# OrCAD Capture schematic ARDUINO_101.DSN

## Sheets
1 04: IO_ARDUINO_5V_Tol: size Custom; title: ARDUNIO 101; rev: 1; company: New Devices Group; note: SCHEM FOR TA=H94227
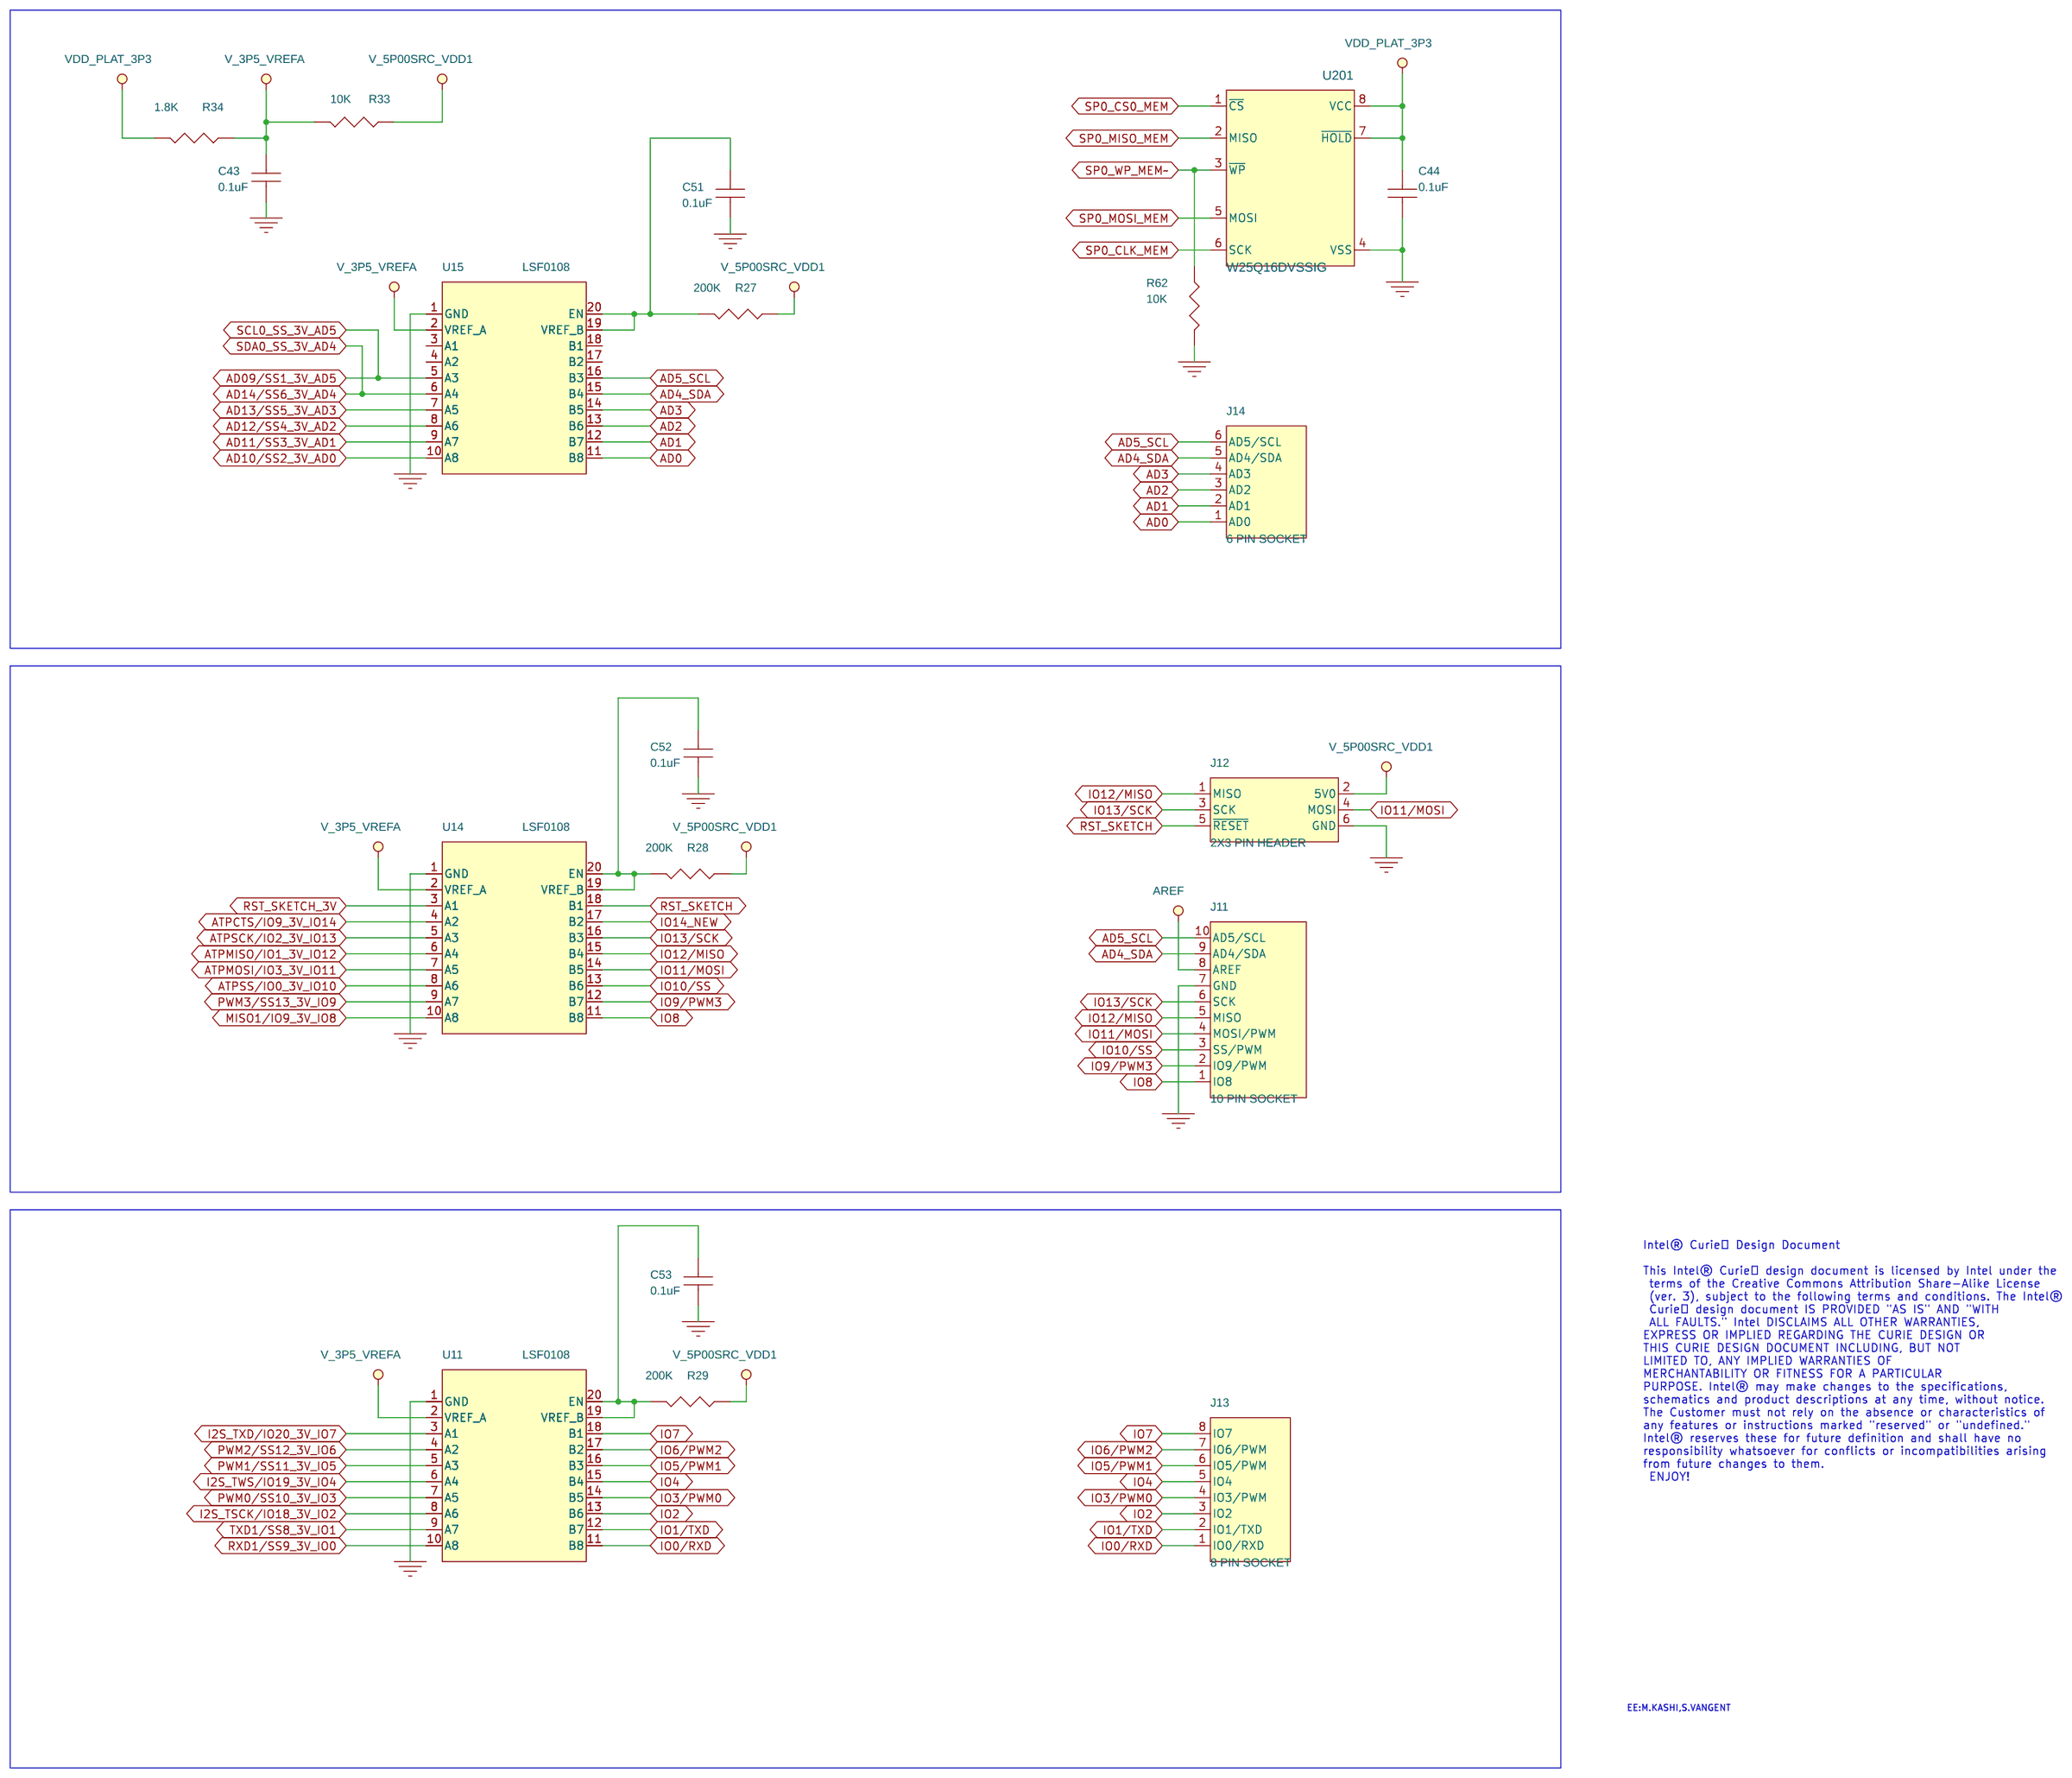
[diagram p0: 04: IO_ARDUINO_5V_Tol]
2 03: Curie: size Custom; rev: A
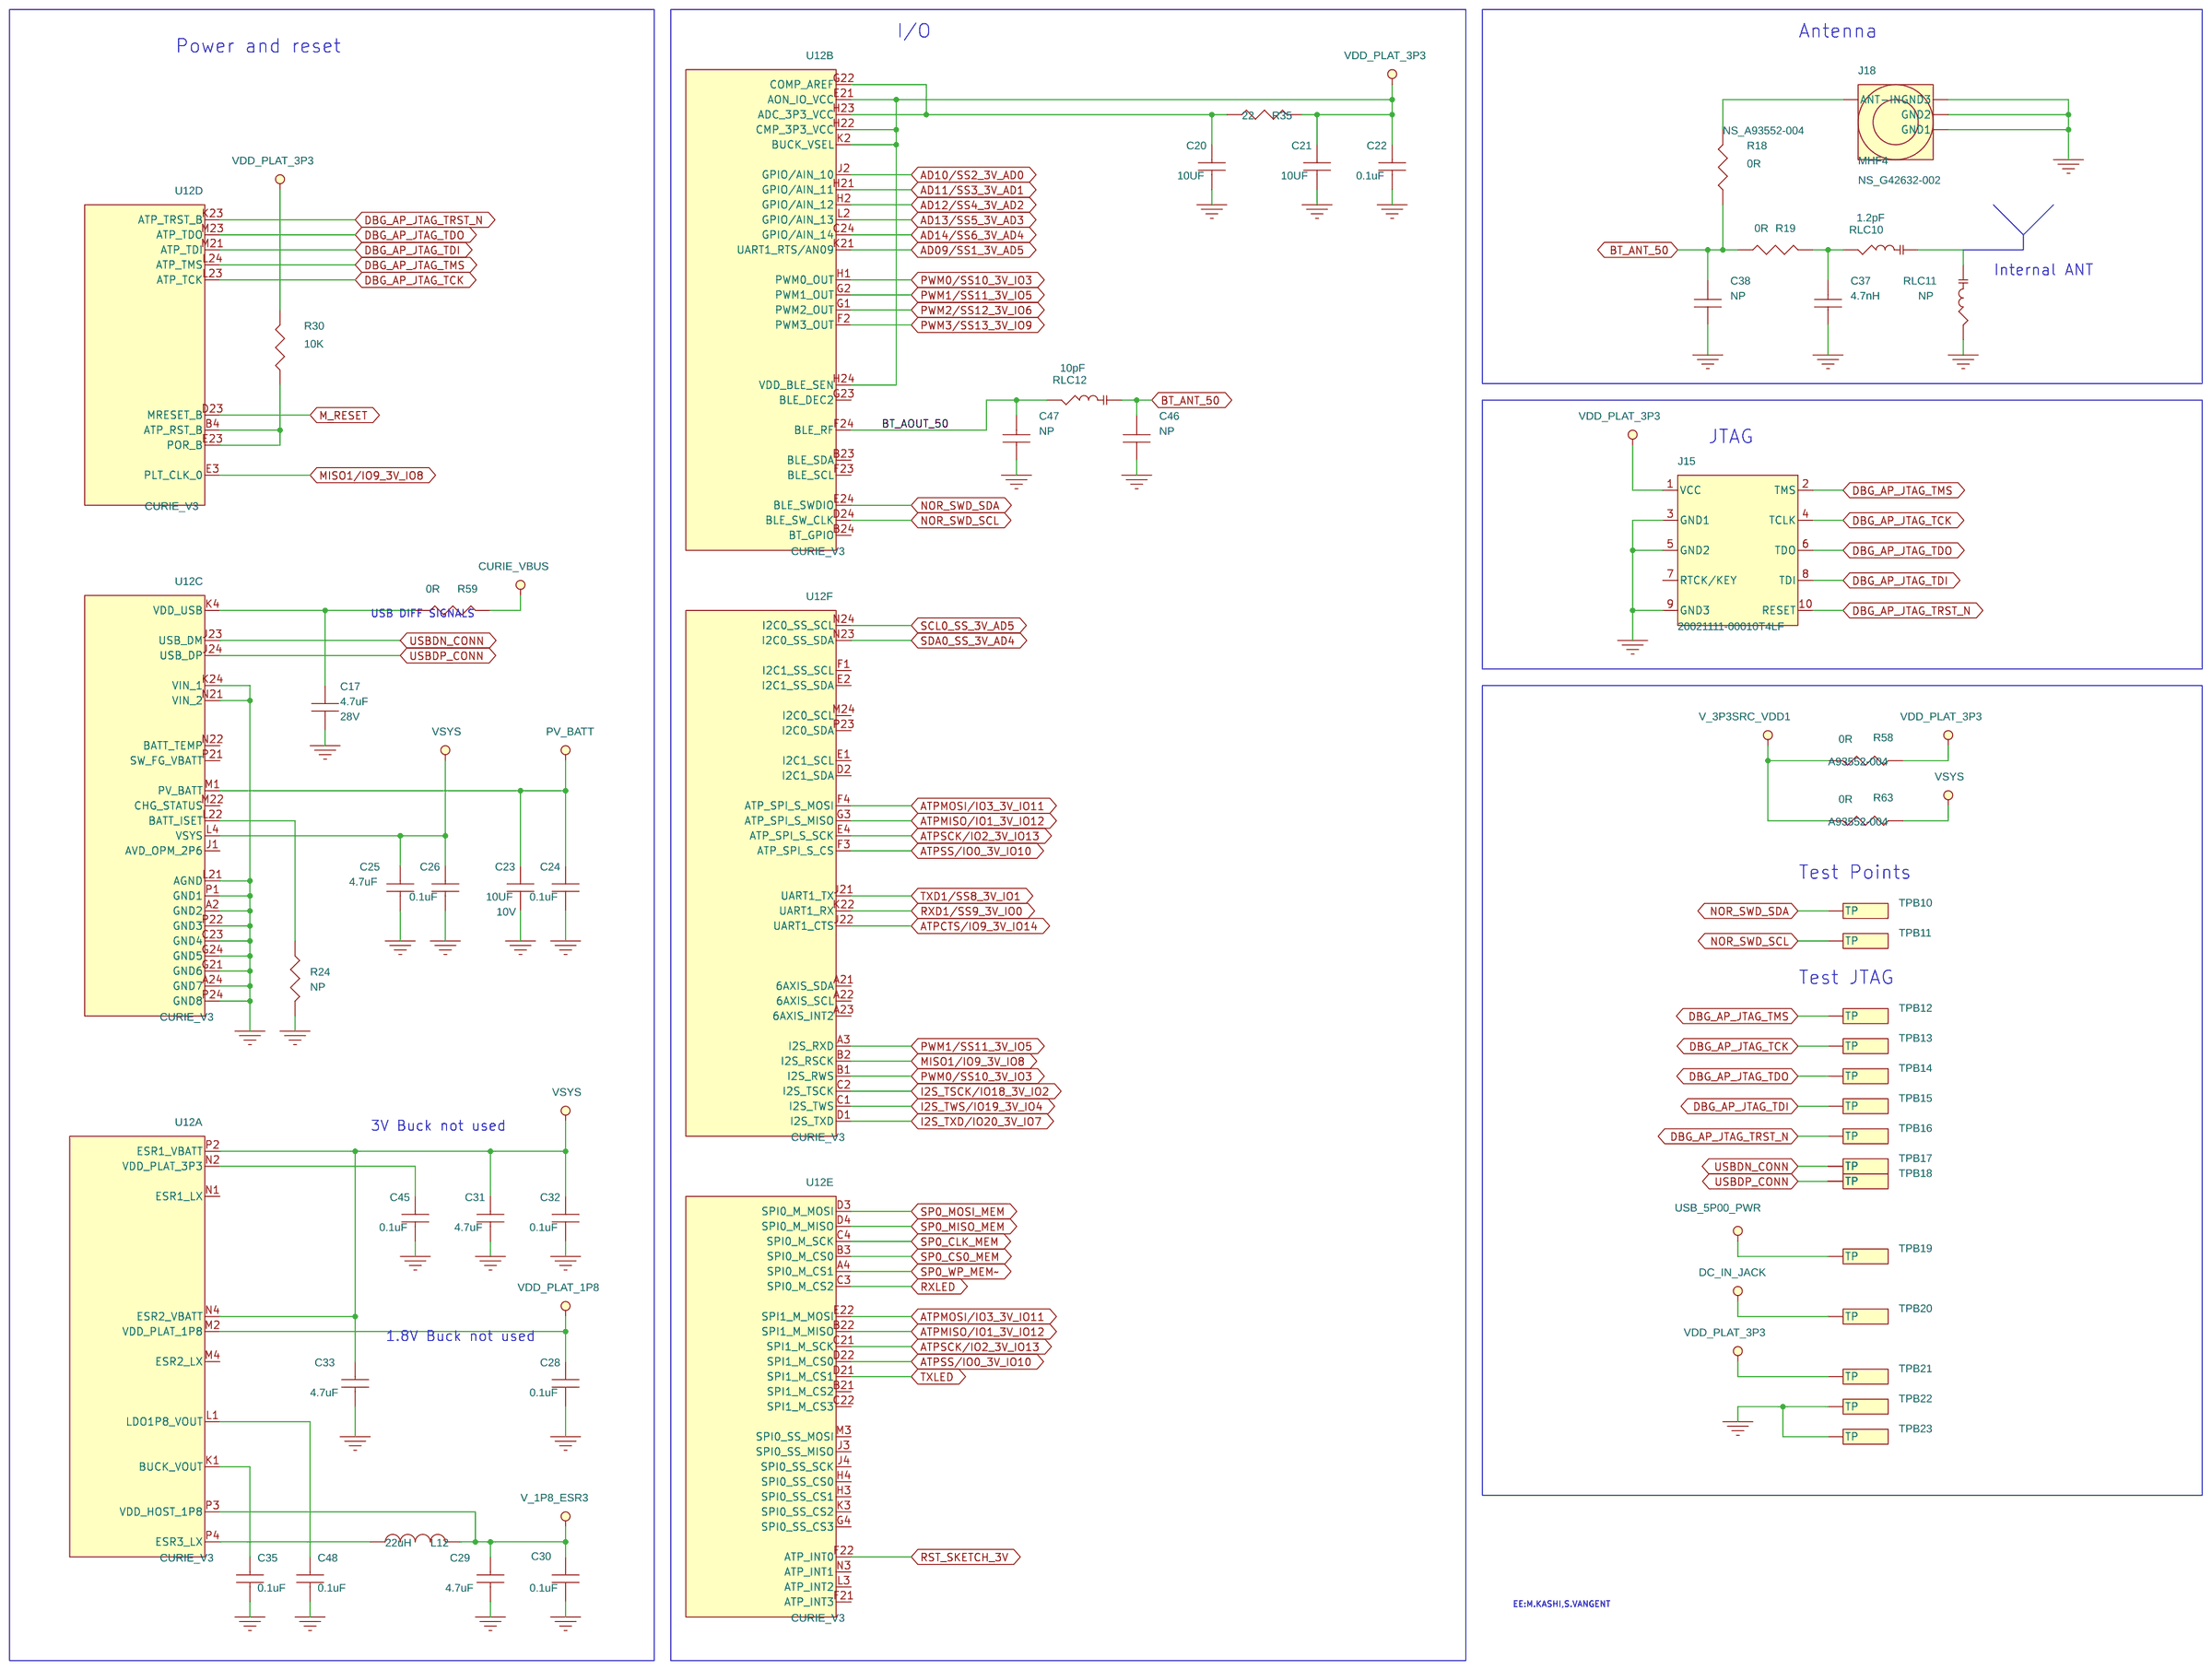
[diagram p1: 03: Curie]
3 02: Power & Connectors: size Custom
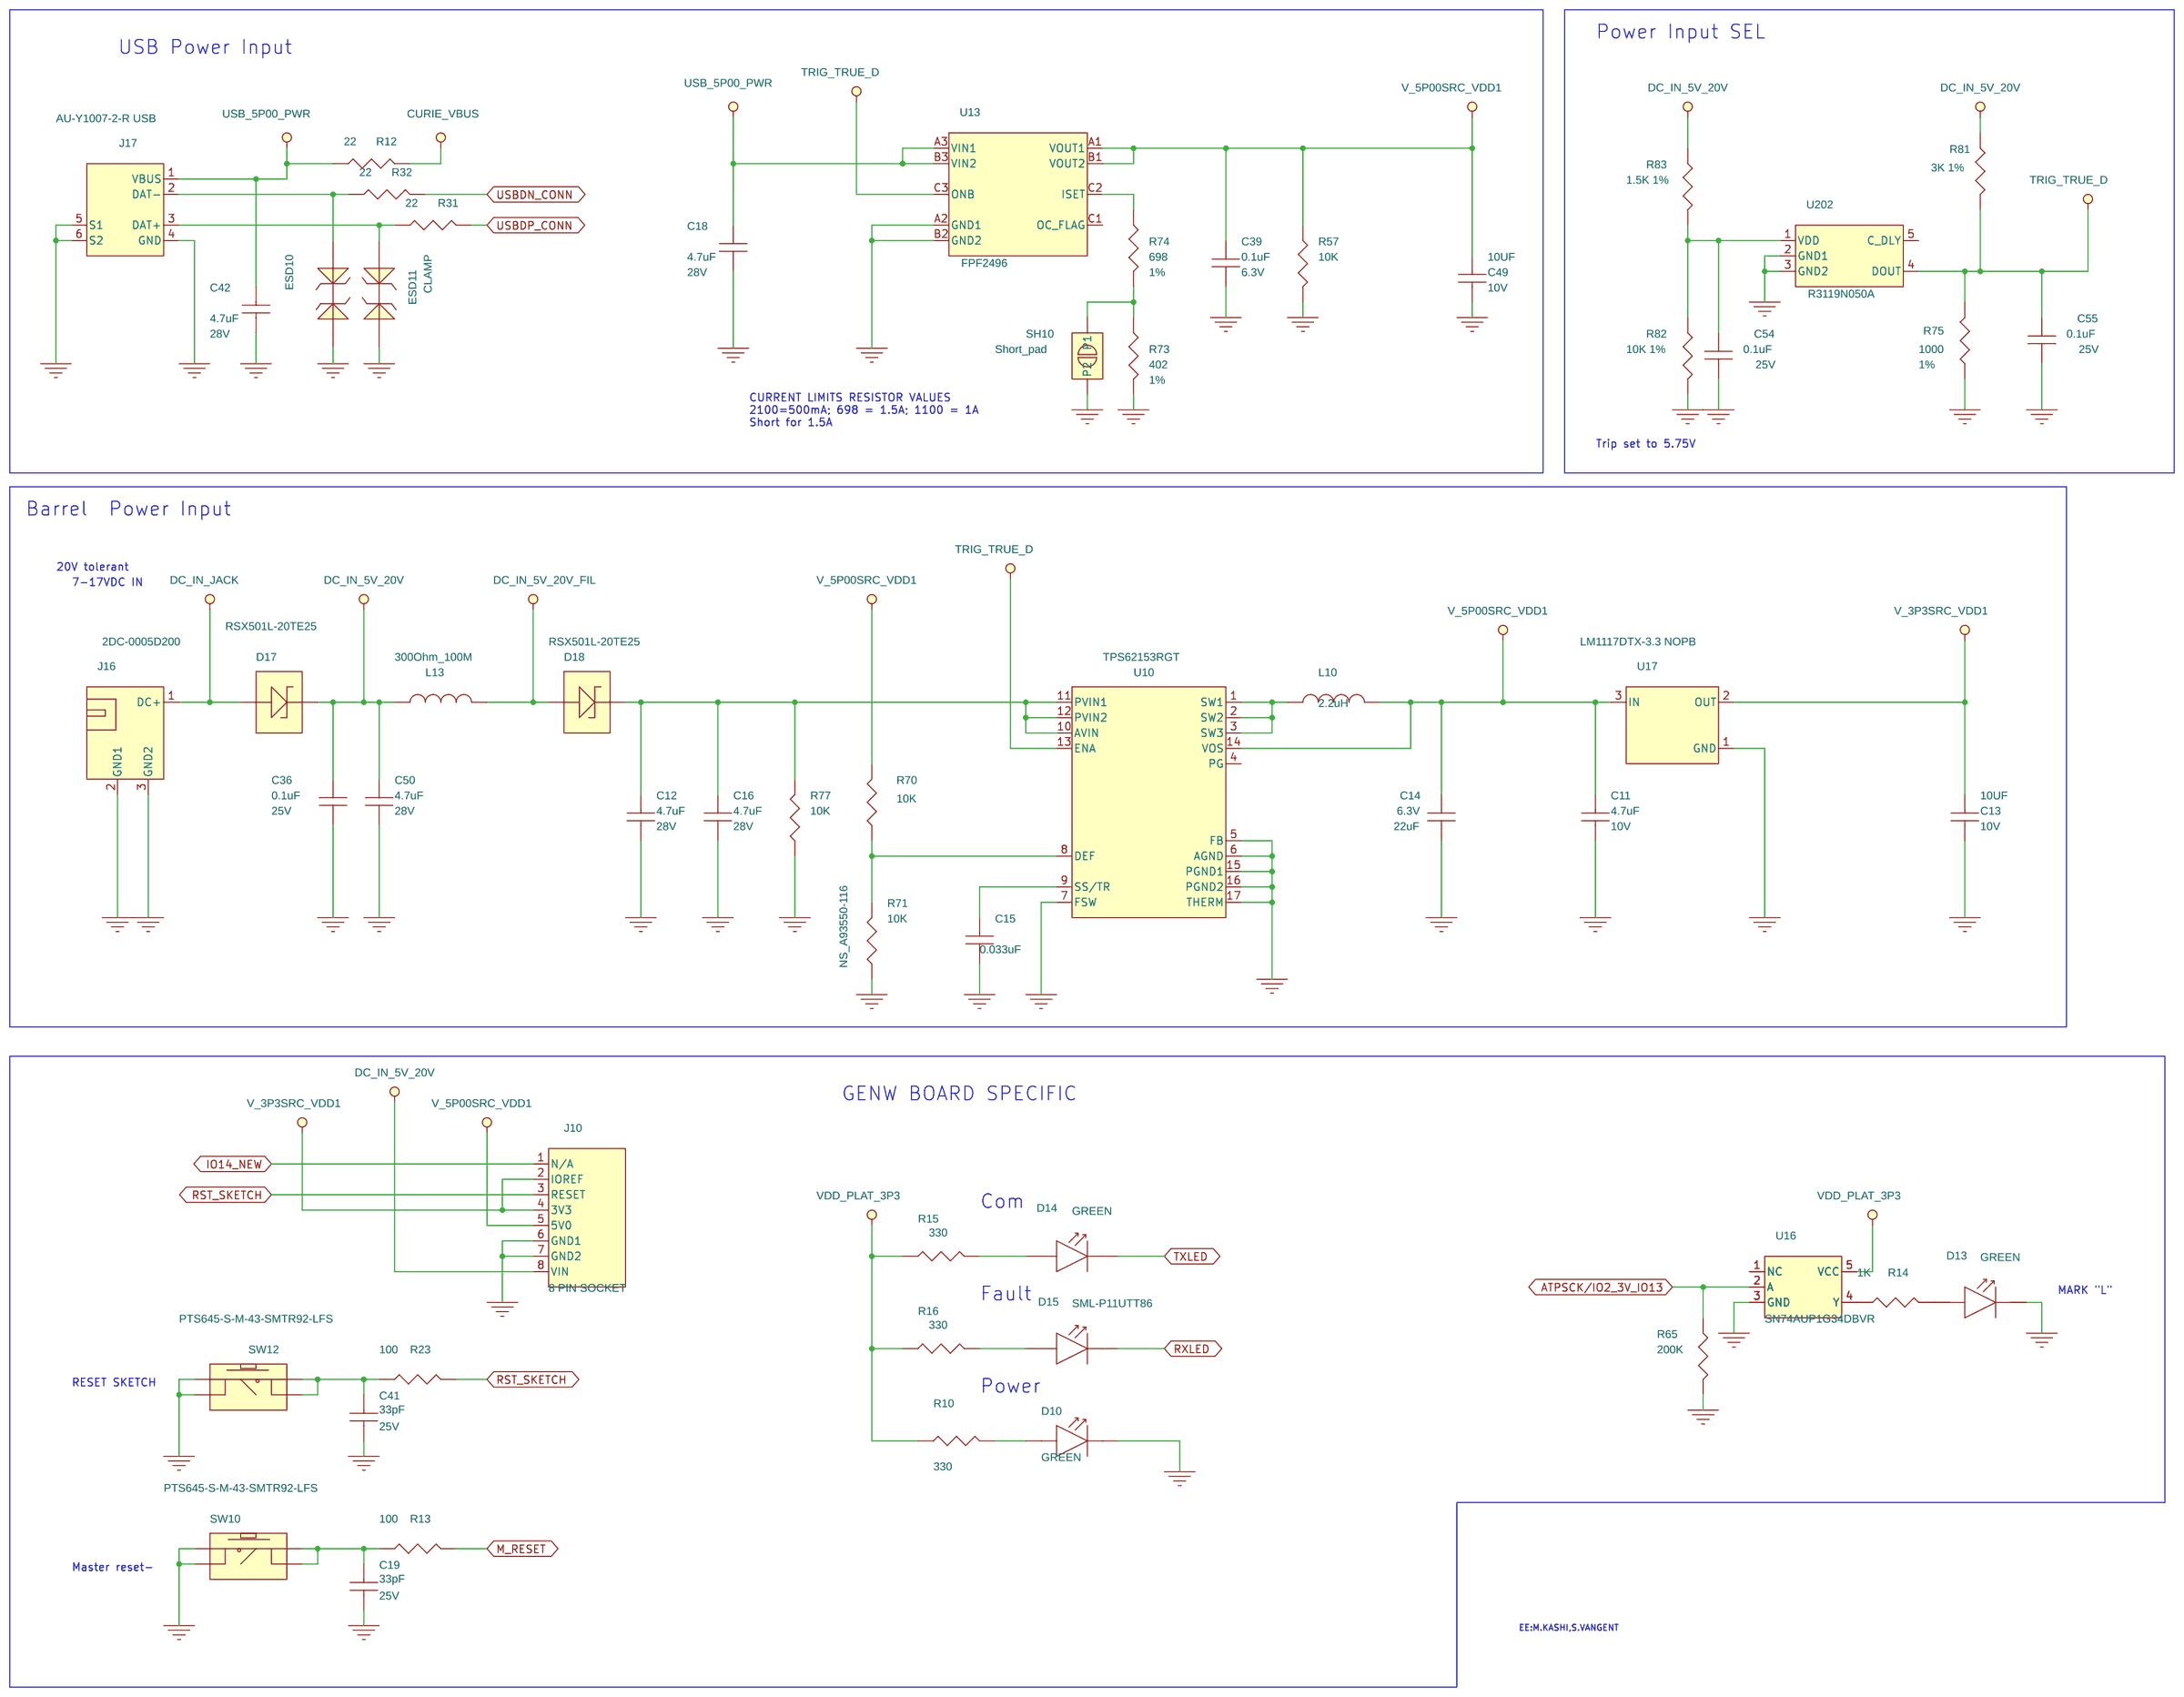
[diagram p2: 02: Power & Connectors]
4 01: Block Diagram and Revs
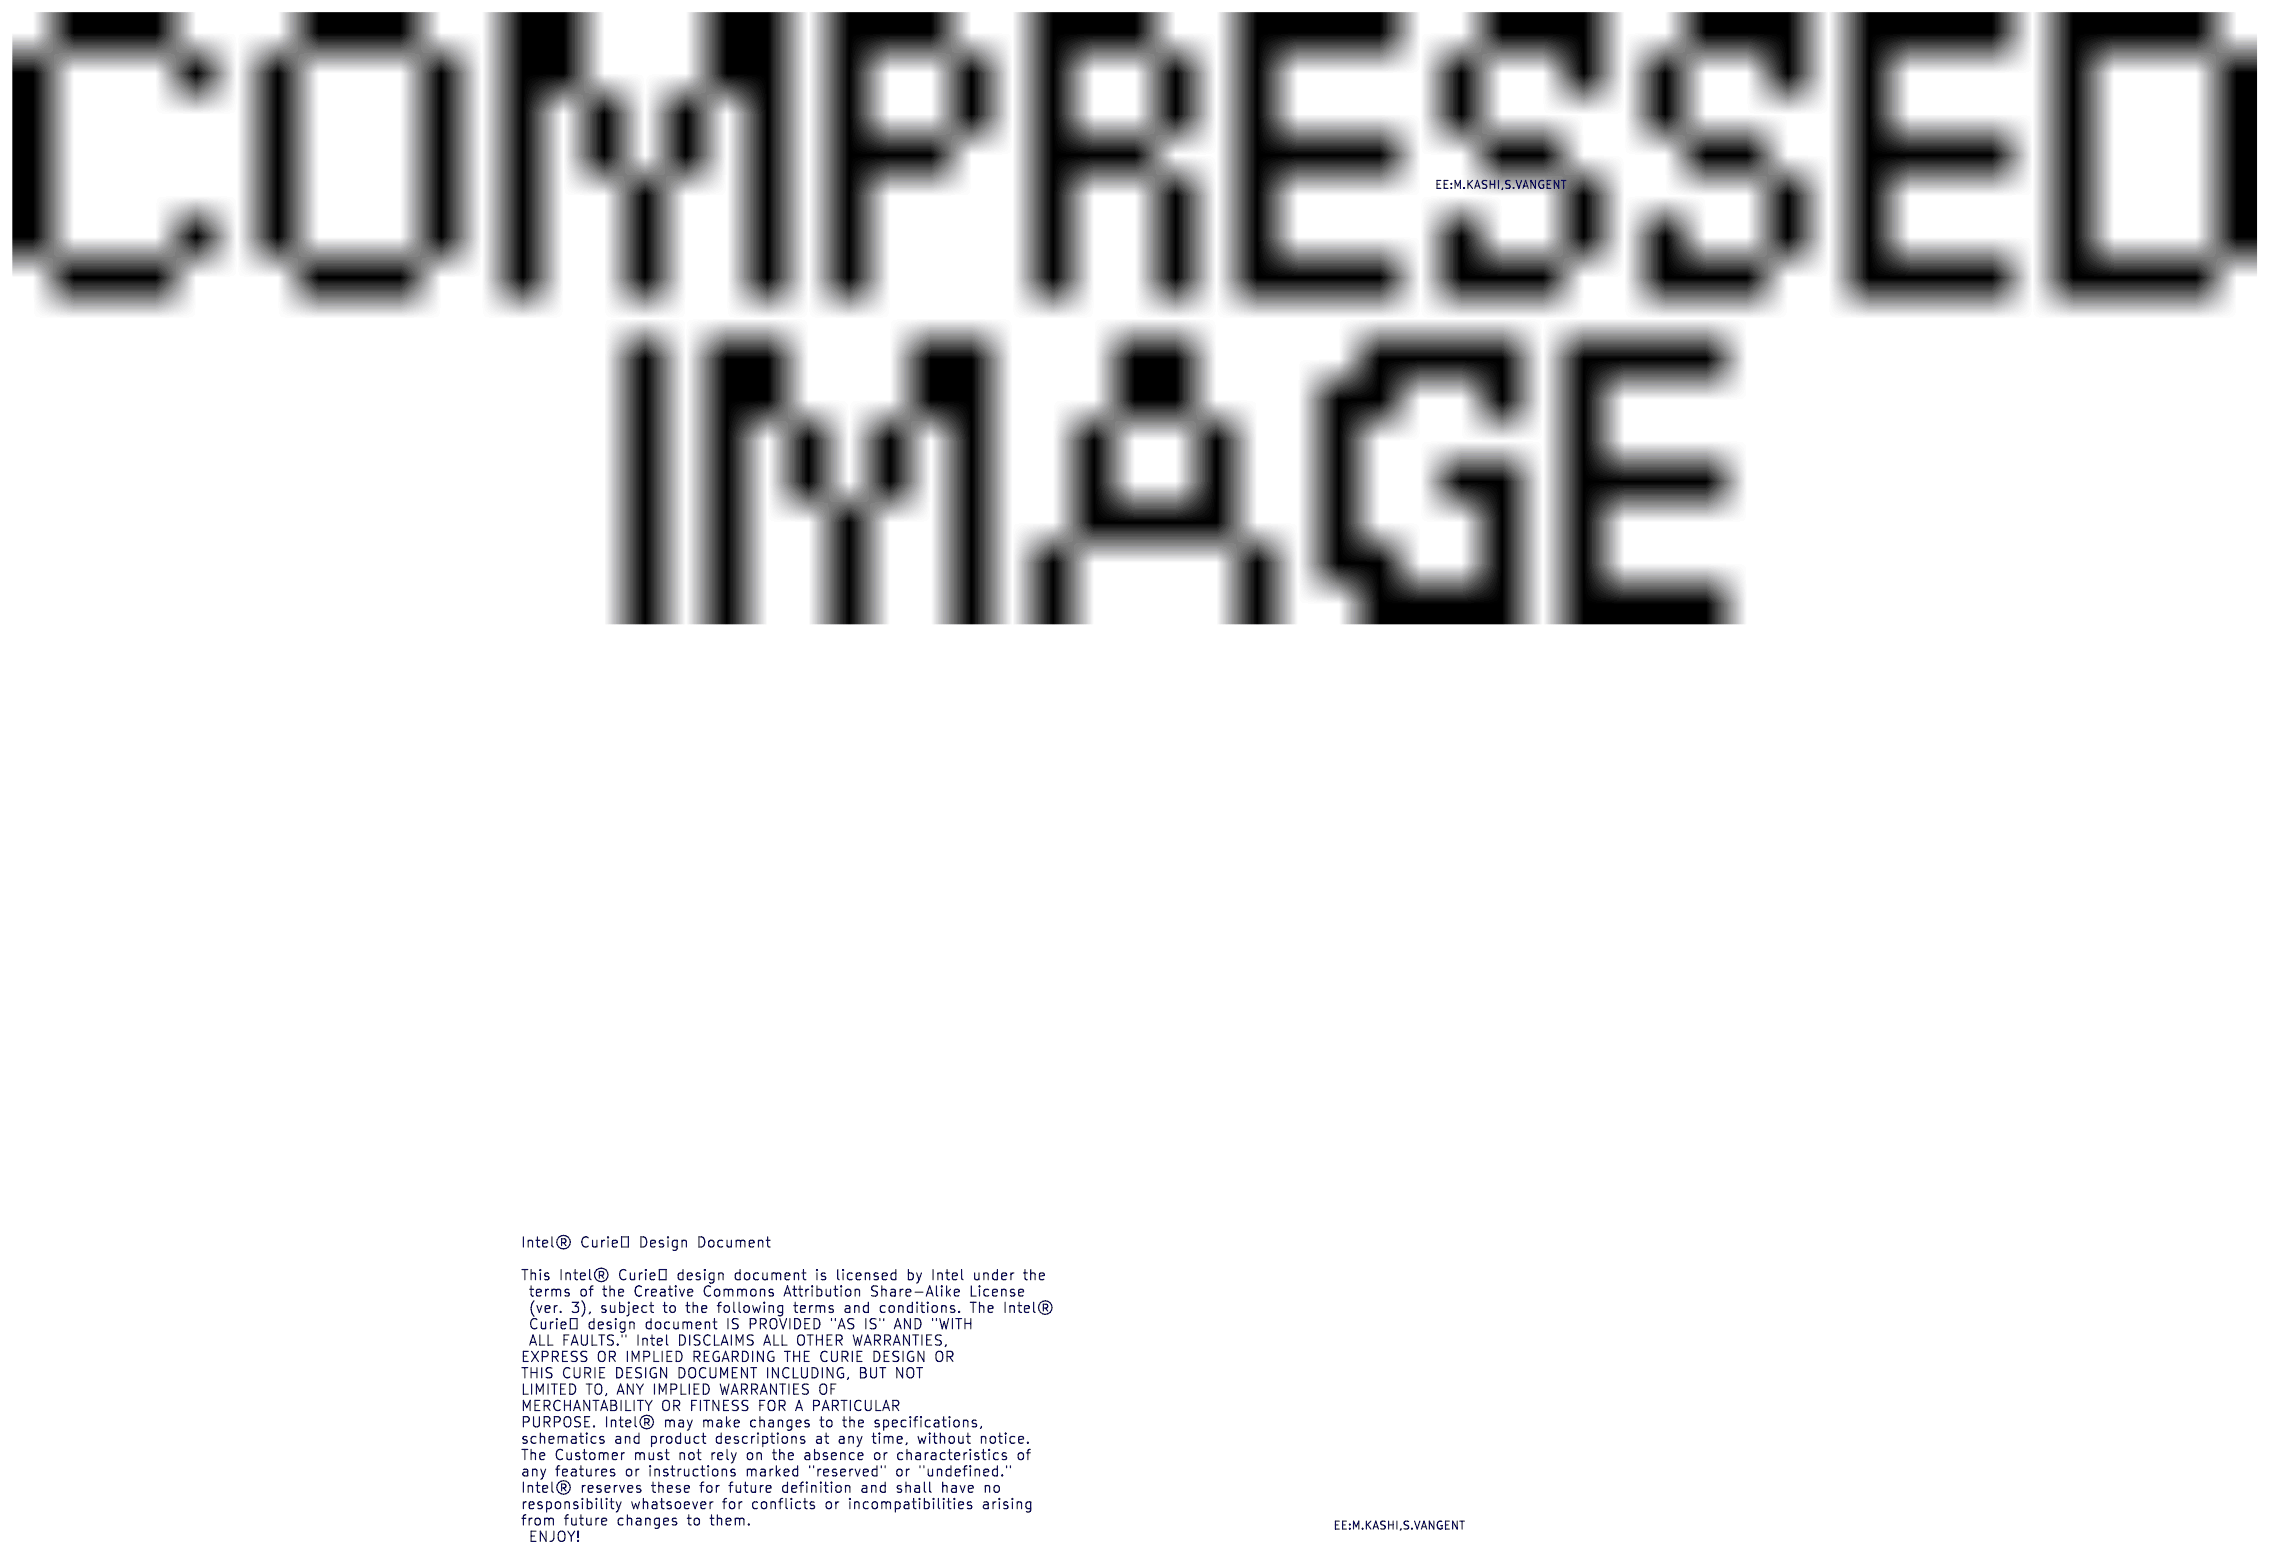
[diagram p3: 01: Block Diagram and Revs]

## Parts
sheet 02: Power & Connectors
C11  4.7uF  [0603X90H]
C12  4.7uF  [0603X90H]
C13  10UF  [0603X90H]
C14  22uF  [0603X90H]
C15  0.033uF  [0603X90H]
C16  4.7uF  [0603X90H]
C18  4.7uF  [0603X90H]
C19  33pF  [0603X90H]
C36  0.1uF  [0603X90H]
C39  0.1uF  [0603X90H]
C41  33pF  [0603X90H]
C42  4.7uF  [0603X90H]
C49  10UF  [0603X90H]
C50  4.7uF  [0603X90H]
C54  0.1uF  [0603X90H]
C55  0.1uF  [0603X90H]
D10  GREEN  [LED_100X60X25H_SMLP13]
D13  GREEN  [LED_100X60X25H_SMLP13]
D14  GREEN  [LED_100X60X25H_SMLP13]
D15  SML-P11UTT86  [LED_100X60X25H_SMLP13]
D17  RSX501L-20TE25  [DIO2_450X260X220H]
D18  RSX501L-20TE25  [DIO2_450X260X220H]
ESD10  CLAMP  [DIO_SOD882]
ESD11  CLAMP  [DIO_SOD882]
J10  8 PIN SOCKET  [CONF1X8-254P_2104X240X850H_TH]
J16  2DC-0005D200  [CON_JACK_880X1350X1135H_EJ508A]
J17  AU-Y1007-2-R USB  [CON_USB_1204X1650X1115_AUY1007]
L10  2.2uH  [0806X100H]
L13  300Ohm_100M  [0603X90H]
R10  330  [0603X90H]
R12  22  [0603X90H]
R13  100  [0603X90H]
R14  1K  [0603X90H]
R15  330  [0603X90H]
R16  330  [0603X90H]
R23  100  [0603X90H]
R31  22  [0603X90H]
R32  22  [0603X90H]
R57  10K  [0603X90H]
R65  200K  [0603X90H]
R70  10K  [0603X90H]
R71  10K  [0603X90H]
R73  402  [0603X90H]
R74  698  [0603X90H]
R75  1000  [0603X90H]
R77  10K  [0603X90H]
R81  3K 1%  [0603X90H]
R82  10K 1%  [0603X90H]
R83  1.5K 1%  [0603X90H]
SH10  Short_pad  [SHORT_140X180]
SW10  PTS645-S-M-43-SMTR92-LFS  [SW4_600X600X430H_SM_PTS645]
SW12  PTS645-S-M-43-SMTR92-LFS  [SW4_600X600X430H_SM_PTS645]
U10  TPS62153RGT  [QFN16-50P_300X300X100H_TR]
U13  FPF2496  [BGA9_3X3-40P_121X121X63H]
U16  SN74AUP1G34DBVR  [SOT23-5_160X290X145H]
U17  LM1117DTX-3.3 NOPB  [DPAK-3P_658X610X238H]
U202  R3119N050A  [SOT23-5_160X290X120H]
sheet 03: Curie
C17  4.7uF  [0603X90H]
C20  10UF  [0603X90H]
C21  10UF  [0603X90H]
C22  0.1uF  [0603X90H]
C23  10UF  [0603X90H]
C24  0.1uF  [0603X90H]
C25  4.7uF  [0603X90H]
C26  0.1uF  [0603X90H]
C28  0.1uF  [0603X90H]
C29  4.7uF  [0603X90H]
C30  0.1uF  [0603X90H]
C31  4.7uF  [0603X90H]
C32  0.1uF  [0603X90H]
C33  4.7uF  [0603X90H]
C35  0.1uF  [0603X90H]
C37  4.7nH  [0603X90H]
C38  NP  [0603X90H]
C45  0.1uF  [0603X90H]
C46  NP  [0603X90H]
C47  NP  [0603X90H]
C48  0.1uF  [0603X90H]
J15  20021111-00010T4LF  [CONM2X5-127P_1270X559X533H_TH]
J18  MHF4  [CONN_COAX_MHF4]
L12  22uH  [COIL_300X300X120H_NRH3012]
R18  0R  [0603X90H]
R19  0R  [0603X90H]
R24  NP  [0603X90H]
R30  10K  [0603X90H]
R35  22  [0603X90H]
R58  0R  [0603X90H]
R59  0R  [0603X90H]
R63  0R  [0603X90H]
RLC10  1.2pF  [0603X90H]
RLC11  NP  [0603X90H]
RLC12  10pF  [0603X90H]
TPB10  T_POINT  [TP40]
TPB11  T_POINT  [TP40]
TPB12  T_POINT  [TP40]
TPB13  T_POINT  [TP40]
TPB14  T_POINT  [TP40]
TPB15  T_POINT  [TP40]
TPB16  T_POINT  [TP40]
TPB17  T_POINT  [TP40]
TPB18  T_POINT  [TP40]
TPB19  T_POINT  [TP40]
TPB20  T_POINT  [TP40]
TPB21  T_POINT  [TP40]
TPB22  T_POINT  [TP40]
TPB23  T_POINT  [TP40]
U12  CURIE_V3  [BGA111_14X24-57P_805X1100X150H]  (sections A,B,C,D,E,F)
sheet 04: IO_ARDUINO_5V_Tol
C43  0.1uF  [0603X90H]
C44  0.1uF  [0603X90H]
C51  0.1uF  [0603X90H]
C52  0.1uF  [0603X90H]
C53  0.1uF  [0603X90H]
J11  10 PIN SOCKET  [CONF1X10-254P_2612X240X850H_TH]
J12  2X3 PIN HEADER  [CONM2X3-254P_762X500X860H_TH]
J13  8 PIN SOCKET  [CONF1X8-254P_2104X240X850H_TH]
J14  6 PIN SOCKET  [CONF1X6-254P_1596X240X850H_TH]
R27  200K  [0603X90H]
R28  200K  [0603X90H]
R29  200K  [0603X90H]
R33  10K  [0603X90H]
R34  1.8K  [0603X90H]
R62  10K  [0603X90H]
U11  LSF0108  [SOIC20-65P_440X650X120H]
U14  LSF0108  [SOIC20-65P_440X650X120H]
U15  LSF0108  [SOIC20-65P_440X650X120H]
U201  W25Q16DVSSIG  [SOIC8-127P_528X528X216H]

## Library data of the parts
C11 C25 C29 C31 C33 = CAP_NP: CAP CER 4.7uF 10V 10% X5R 0603; BSI: 120-00020-01; Digikey Partnumber: 587-1441-2-ND; IPN: 602433-096; Manufacturer: Taiyo Yuden; Manufacturer_PN: LMK107BJ475KA-T; Rating: 10V
C12 C16-C18 C42 C50 = CAP_NP: CAP CER 4.7uF 10V 10% X5R 0603; BSI: 120-00020-01; Digikey Partnumber: 587-1441-2-ND; IPN: 602433-107; Manufacturer: Taiyo Yuden; Manufacturer_PN: LMK107BJ475KA-T; Rating: 28V
C13 C20 C23 C49 = CAP-NP_0: Digikey Partnumber: 587-3383-6-ND; IPN: H63563-001; Rating: 10V; TOL: 20%
C14 = CAP-NP_0: Digikey Partnumber: 1276-1193-6-ND; IPN: 602433-105; Rating: 6.3V
C15 = CAP_NP: CAP CER 0.1UF 10V 20% X5R 0201; BSI: 120-00022-01; Digikey Partnumber: 399-10044-6-ND; IPN: 603269-064; Manufacturer: Murata; Manufacturer_PN: GRM033R61A104ME15D; Rating: 6.3V
C19 C41 = CAP-NP_0: Digikey Partnumber: 1276-1070-6-ND; IPN: 603275-166; Rating: 25V
C36 C54 C55 = CAP-NP_0: IPN: 602433-037; Rating: 25V; VALUE_B1: 10uF
C39 = CAP-NP_0: Digikey Partnumber: 490-1532-6-ND; IPN: 602433-037; Intel_B1 PN------: 602433-086; Rating: 6.3V; VALUE_B1: 10uF
D10 D13 D14 = LED_6: Digikey Partnumber: 511-1592-1-ND; IPN: G46308-001
D15 = LED_6: Digikey Partnumber: 511-1593-6-ND; IPN: H82742-001
D17 D18 = BAS40SL_1: Digikey Partnumber: B220A-FDIDKR-ND; IPN: G93253-001
ESD10 ESD11 = AOZ8131DI-05L_100312_000: Digikey Partnumber: 785-1645-6-ND; IPN: H92509-001
J10 = 8_PIN_SOCKET: Digikey Partnumber: MOUSER_538-90147-1108; IPN: H76806-001
J16 = EJ508A_0: Digikey Partnumber: EJ508A-ND; IPN: G60557-001
J17 = USB_TYPE_B_2: Digikey Partnumber: AE10333-ND; IPN: H78963-001
L10 = INDCT,PWR,63X79,1.9A,2.2uH: IPN: G84512-001; PART_NUMBER: 652666-053; ROOM: CWS_WLAN
L13 = INDCT,PWR,63X79,1.9A,2.2uH: DEVICE: MI0603L301R-00; Digikey Partnumber: 240-2374-1-ND; IPN: H86252-001; PART_NUMBER: 652666-053; ROOM: CWS_WLAN
R10 = RESISTOR: RES 2M OHM 1/20W 1% 0201 SMD; BSI: 180-00057-01; IPN: A93551-037; Manufacturer: Rohm; Manufacturer_PN: MCR006YRTF2004
R12 R31 R32 R35 = RESISTOR: RES 2M OHM 1/20W 1% 0201 SMD; BSI: 180-00057-01; Digikey Partnumber: RHM22CGDKR-ND; IPN: A93553-163; Manufacturer: Rohm; Manufacturer_PN: MCR006YRTF2004
R13 R23 = RESISTOR: RES 2M OHM 1/20W 1% 0201 SMD; BSI: 180-00057-01; Digikey Partnumber: RHM2000KCBTR-ND; IPN: A93550-026; Manufacturer: Rohm; Manufacturer_PN: MCR006YRTF2004
R14 = RESISTOR: RES 2M OHM 1/20W 1% 0201 SMD; BSI: 180-00057-01; Digikey Partnumber: P1.0KGDKR-ND; IPN: A93553-043; Manufacturer: Rohm; Manufacturer_PN: MCR006YRTF2004
R15 R16 = RESISTOR: RES 2M OHM 1/20W 1% 0201 SMD; BSI: 180-00057-01; Digikey Partnumber: P1.0KGDKR-ND; IPN: A93551-037; Manufacturer: Rohm; Manufacturer_PN: MCR006YRTF2004
R57 R70 R77 R82 = R_5: Digikey Partnumber: P10KGDKR-ND; IPN: A93550-116; TOL: <TOL>
R27-R29 R65 = RESISTOR: RES 2M OHM 1/20W 1% 0201 SMD; BSI: 180-00057-01; Digikey Partnumber: RHM2000KCBTR-ND; IPN: A93551-104; Manufacturer: Rohm; Manufacturer_PN: MCR006YRTF2004
R71 = R_5: Digikey Partnumber: P10KGDKR-ND; IPN: NS_A93550-116; TOL: <TOL>
R73 = R_5: Digikey Partnumber: P2.32KHDKR-ND; IPN: A93550-232; TOL: 1%
R74 = R_5: Digikey Partnumber: P2.32KHDKR-ND; IPN: A93550-240; TOL: 1%
R75 = R_5: Digikey Partnumber: P2.32KHDKR-ND; IPN: A93550-067; TOL: 1%
R81 = R_5: Digikey Partnumber: P10KGDKR-ND; IPN: A93550-529; TOL: <TOL>
R83 = R_5: Digikey Partnumber: P10KGDKR-ND; IPN: A93550-076; TOL: <TOL>
SH10 = Shorting_pad_2: IPN: TEST_POINT
SW10 SW12 = TCFC2QR1_1: IPN: H85607-001
U10 = TPS62143RGT_5: IPN: H85933-001
U13 = FPF2496: Digikey Partnumber: FPF2496UCXDKR-ND; IPN: H76941-001
U16 = SN74AUP1G07DBVR: Digikey Partnumber: 296-32256-6-ND; IPN: E76671-001
U17 = NCP1117DT33T5G_0: IPN: C83164-001
U202 = R3120NxxxA_0: IPN: H98436-001
C21 = CAP_NP: CAP CER 0.1UF 10V 20% X5R 0201; BSI: 120-00022-01; Digikey Partnumber: 587-3383-6-ND; IPN: H63563-001; Manufacturer: Murata; Manufacturer_PN: GRM033R61A104ME15D; Rating: 10V; TOL: 20%
C22 C24 C26 C28 C30 C32 C35 C43-C45 C48 C51-C53 = CAP_NP: CAP CER 0.1UF 10V 20% X5R 0201; BSI: 120-00022-01; Digikey Partnumber: 490-1532-6-ND; IPN: 602433-037; Manufacturer: Murata; Manufacturer_PN: GRM033R61A104ME15D; Rating: 6.3V
C37 = CAP_NP_0: Digikey Partnumber: NA; IPN: 202287-036
C38 C46 C47 = CAP_NP_0: Digikey Partnumber: NA; IPN: NS_108506-004
J15 = SHF-105-01-L-D-TH_0: Digikey Partnumber: 609-3712-ND; IPN: H92285-001
J18 = COAX-CONN_2: Digikey Partnumber: NA; IPN: NS_G42632-002
L12 = INDCT,PWR,22uH: Digikey Partnumber: 587-2588-6-ND
R18 = RESD,0402,5%,1_16W,0: RES D,0402,0.00 OHM,5.00%,1/16W; Digikey Partnumber: P0.0GDKR-ND; IPN: NS_A93552-004; Manufacturer: KOA SPEER ELECTRONICS; Manufacturer_PN: RK73Z1ETTP
R19 = RESD,0402,5%,1_16W,0: RES D,0402,0.00 OHM,5.00%,1/16W; Digikey Partnumber: P0.0GDKR-ND; IPN: A93552-004; Manufacturer: KOA SPEER ELECTRONICS; Manufacturer_PN: RK73Z1ETTP; Mfgr part no: A93552-004
R24 = R_5: Digikey Partnumber: NA; IPN: NS_108506-004
R30 R33 R62 = R_5: Digikey Partnumber: P10KGDKR-ND; IPN: A93550-116
R58 R63 = RESD,0402,5%,1_16W,0: RES D,0402,0.00 OHM,5.00%,1/16W; Digikey Partnumber: P0.0GDKR-ND; IPN: A93552-004; Manufacturer: KOA SPEER ELECTRONICS; Manufacturer_PN: RK73Z1ETTP
R59 = RESISTOR: RES 2M OHM 1/20W 1% 0201 SMD; BSI: 180-00057-01; Digikey Partnumber: P0.0GDKR-ND; IPN: A93552-004; Manufacturer: Rohm; Manufacturer_PN: MCR006YRTF2004; Rating: 1/16W; TOL: 5%
RLC10 = RLC: Digikey Partnumber: 712-1301-2-ND; IPN: 603275-157
RLC11 = RLC: Digikey Partnumber: PCD2005DKR-ND; IPN: NS_108506-004
RLC12 = RLC: Digikey Partnumber: P0.0GDKR-ND; IPN: 603275-158
TPB10-TPB23 = T_POINT_S_3: Digikey Partnumber: NA; IPN: NO_STUFF
U12 = CURIE_23: Digikey Partnumber: NA; IPN: NEED_IPN
J11 = 10_PIN_SOCKET_2: Digikey Partnumber: MOUSER_538-90147-1110; IPN: G79666-001
J12 = jumper_0: Digikey Partnumber: 952-2121-ND; IPN: H76811-001
J13 = 8_PIN_SOCKET_0: Digikey Partnumber: MOUSER_538-90147-1108; IPN: H76806-001
J14 = 8_PIN_SOCKET_3: Digikey Partnumber: MOUSER_538-90147-1106; IPN: H98107-001; Intel_B1 PN------: H98107-001
R34 = R_5: Digikey Partnumber: P1.8KGDKR-ND; IPN: A93550-511
U11 U14 U15 = LSF0108: Digikey Partnumber: 296-37828-6-ND; IPN: H73147-001
U201 = M25P16_1: IC FLASH 128MBIT 104MHZ 8WSON; BSI: 150-00027-01; Digikey Partnumber: W25Q16DVSSIG-ND; Geometry.Height: 0.8mm; IPN: E68833-002; Manufacturer: Macronix; Manufacturer_PN: MX25L12835FZNI-10G; Mfgr part no: SST25VF080B-50-4C-QAF

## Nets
GND: C11.2 C12.2 C13.2 C14.2 C15.2 C16.2 C17.2 C18.2 C19.2 C20.2 C21.2 C22.2 C23.2 C24.2 C25.2 C26.2 C28.2 C29.2 C30.2 C31.2 C32.2 C33.2 C35.2 C36.2 C37.1 C38.1 C39.2 C41.2 C42.2 C43.2 C44.2 C45.2 C46.1 C47.1 C48.2 C49.2 C50.2 C51.2 C52.2 C53.2 C54.2 C55.2 D10.K D13.K ESD10.2 ESD11.2 J10.6(GND1) J10.7(GND2) J11.7(GND) J12.6(GND) J15.3(GND1) J15.5(GND2) J15.9(GND3) J16.2(GND1) J16.3(GND2) J17.4(GND) J17.5(S1) J17.6(S2) J18.2(GND1) J18.3(GND2) J18.4(GND3) R24.1 R57.1 R62.2 R65.2 R71.2 R73.1 R75.2 R77.2 R82.2 RLC11.1 SH10.2(P2) SW10.1 SW10.2 SW12.3 SW12.4 TPB22.1(TP) TPB23.1(TP) U10.5(FB) U10.6(AGND) U10.7(FSW) U10.15(PGND1) U10.16(PGND2) U10.17(THERM) U11.1(GND) U12.A2(GND2) U12.A24(GND7) U12.C23(GND4) U12.G21(GND6) U12.G24(GND5) U12.K24(VIN_1) U12.L21(AGND) U12.N21(VIN_2) U12.P1(GND1) U12.P22(GND3) U12.P24(GND8) U13.A2(GND1) U13.B2(GND2) U14.1(GND) U15.1(GND) U16.3(GND) U17.1(GND) U201.4(VSS) U202.2(GND1) U202.3(GND2)
VDD_PLAT_1P8: C28.1 U12.M2(VDD_PLAT_1P8)
VDD_PLAT_3P3: C21.1 C22.1 C44.1 J15.1(VCC) R10.1 R15.1 R16.1 R30.1 R34.1 R35.2 R58.1 TPB21.1(TP) U12.E21(AON_IO_VCC) U12.H22(CMP_3P3_VCC) U12.H24(VDD_BLE_SEN) U12.K2(BUCK_VSEL) U16.5(VCC) U201.7(~{HOLD}) U201.8(VCC)
AD0: J14.1(AD0) U15.11(B8)
AD1: J14.2(AD1) U15.12(B7)
AD2: J14.3(AD2) U15.13(B6)
AD3: J14.4(AD3) U15.14(B5)
AD4_SDA: J11.9(AD4/SDA) J14.5(AD4/SDA) U15.15(B4)
AD5_SCL: J11.10(AD5/SCL) J14.6(AD5/SCL) U15.16(B3)
AD09/SS1_3V_AD5: U12.K21(UART1_RTS/AN09) U12.N24(I2C0_SS_SCL) U15.5(A3)
AD10/SS2_3V_AD0: U12.J2(GPIO/AIN_10) U15.10(A8)
AD11/SS3_3V_AD1: U12.H21(GPIO/AIN_11) U15.9(A7)
AD12/SS4_3V_AD2: U12.H2(GPIO/AIN_12) U15.8(A6)
AD13/SS5_3V_AD3: U12.L2(GPIO/AIN_13) U15.7(A5)
AD14/SS6_3V_AD4: U12.C24(GPIO/AIN_14) U12.N23(I2C0_SS_SDA) U15.6(A4)
AREF: J11.8(AREF)
ATPCTS/IO9_3V_IO14: U12.J22(UART1_CTS) U14.4(A2)
ATPMISO/IO1_3V_IO12: U12.B22(SPI1_M_MISO) U12.G3(ATP_SPI_S_MISO) U14.6(A4)
ATPMOSI/IO3_3V_IO11: U12.E22(SPI1_M_MOSI) U12.F4(ATP_SPI_S_MOSI) U14.7(A5)
ATPSCK/IO2_3V_IO13: R65.1 U12.C21(SPI1_M_SCK) U12.E4(ATP_SPI_S_SCK) U14.5(A3) U16.2(A)
ATPSS/IO0_3V_IO10: U12.D22(SPI1_M_CS0) U12.F3(ATP_SPI_S_CS) U14.8(A6)
BT_ANT_50: C38.2 C46.2 R18.1 R19.1 RLC12.2
BT_AOUT_50: C47.2 RLC12.1 U12.F24(BLE_RF)
CURIE_VBUS: R12.2 R59.2
DBG_AP_JTAG_TCK: J15.4(TCLK) TPB13.1(TP) U12.L23(ATP_TCK)
DBG_AP_JTAG_TDI: J15.8(TDI) TPB15.1(TP) U12.M21(ATP_TDI)
DBG_AP_JTAG_TDO: J15.6(TDO) TPB14.1(TP) U12.M23(ATP_TDO)
DBG_AP_JTAG_TMS: J15.2(TMS) TPB12.1(TP) U12.L24(ATP_TMS)
DBG_AP_JTAG_TRST_N: J15.10(RESET) TPB16.1(TP) U12.K23(ATP_TRST_B)
DC_IN_5V_20V: C36.1 C50.1 D17.K J10.8(VIN) L13.1 R81.1 R83.1
DC_IN_5V_20V_FIL: D18.A L13.2
DC_IN_JACK: D17.A J16.1(DC+) TPB20.1(TP)
I2S_TSCK/IO18_3V_IO2: U11.8(A6) U12.C2(I2S_TSCK)
I2S_TWS/IO19_3V_IO4: U11.6(A4) U12.C1(I2S_TWS)
I2S_TXD/IO20_3V_IO7: U11.3(A1) U12.D1(I2S_TXD)
IO0/RXD: J13.1(IO0/RXD) U11.11(B8)
IO1/TXD: J13.2(IO1/TXD) U11.12(B7)
IO2: J13.3(IO2) U11.13(B6)
IO3/PWM0: J13.4(IO3/PWM) U11.14(B5)
IO4: J13.5(IO4) U11.15(B4)
IO5/PWM1: J13.6(IO5/PWM) U11.16(B3)
IO6/PWM2: J13.7(IO6/PWM) U11.17(B2)
IO7: J13.8(IO7) U11.18(B1)
IO8: J11.1(IO8) U14.11(B8)
IO9/PWM3: J11.2(IO9/PWM) U14.12(B7)
IO10/SS: J11.3(SS/PWM) U14.13(B6)
IO11/MOSI: J11.4(MOSI/PWM) J12.4(MOSI) U14.14(B5)
IO12/MISO: J11.5(MISO) J12.1(MISO) U14.15(B4)
IO13/SCK: J11.6(SCK) J12.3(SCK) U14.16(B3)
IO14_NEW: J10.1(N/A) U14.17(B2)
M_RESET: R13.2 U12.D23(MRESET_B)
MISO1/IO9_3V_IO8: U12.B2(I2S_RSCK) U12.E3(PLT_CLK_0) U14.10(A8)
NOR_SWD_SCL: TPB11.1(TP) U12.D24(BLE_SW_CLK)
NOR_SWD_SDA: TPB10.1(TP) U12.E24(BLE_SWDIO)
PV_BATT: C23.1 C24.1 U12.M1(PV_BATT)
PWM0/SS10_3V_IO3: U11.7(A5) U12.B1(I2S_RWS) U12.H1(PWM0_OUT)
PWM1/SS11_3V_IO5: U11.5(A3) U12.A3(I2S_RXD) U12.G2(PWM1_OUT)
PWM2/SS12_3V_IO6: U11.4(A2) U12.G1(PWM2_OUT)
PWM3/SS13_3V_IO9: U12.F2(PWM3_OUT) U14.9(A7)
RST_SKETCH: J10.3(RESET) J12.5(~{RESET}) R23.2 U14.18(B1)
RST_SKETCH_3V: U12.F22(ATP_INT0) U14.3(A1)
RXD1/SS9_3V_IO0: U11.10(A8) U12.K22(UART1_RX)
RXLED: D15.K U12.C3(SPI0_M_CS2)
SP0_CLK_MEM: U12.C4(SPI0_M_SCK) U201.6(SCK)
SP0_CS0_MEM: U12.B3(SPI0_M_CS0) U201.1(~{CS})
SP0_MISO_MEM: U12.D4(SPI0_M_MISO) U201.2(MISO)
SP0_MOSI_MEM: U12.D3(SPI0_M_MOSI) U201.5(MOSI)
SP0_WP_MEM~: R62.1 U12.A4(SPI0_M_CS1) U201.3(~{WP})
TRIG_TRUE_D: C55.1 R75.1 R81.2 U10.13(ENA) U13.C3(ONB) U202.4(DOUT)
TXD1/SS8_3V_IO1: U11.9(A7) U12.J21(UART1_TX)
TXLED: D14.K U12.D21(SPI1_M_CS1)
USB_5P00_PWR: C18.1 C42.1 J17.1(VBUS) R12.1 TPB19.1(TP) U13.A3(VIN1) U13.B3(VIN2)
USBDN_CONN: R32.2 TPB17.1(TP) U12.J23(USB_DM)
USBDP_CONN: R31.2 TPB18.1(TP) U12.J24(USB_DP)
V_1P8_ESR3: C29.1 C30.1 L12.1 U12.P3(VDD_HOST_1P8)
V_3P3SRC_VDD1: C13.1 J10.2(IOREF) J10.4(3V3) R58.2 R63.2 U17.2(OUT)
V_3P5_VREFA: C43.1 R33.2 R34.2 U11.2(VREF_A) U14.2(VREF_A) U15.2(VREF_A)
V_5P00SRC_VDD1: C11.1 C14.1 C39.1 C49.1 J10.5(5V0) J12.2(5V0) L10.2 R27.1 R28.1 R29.1 R33.1 R57.2 R70.1 U10.14(VOS) U13.A1(VOUT1) U13.B1(VOUT2) U17.3(IN)
VSYS: C25.1 C26.1 C31.1 C32.1 C33.1 R63.1 U12.L4(VSYS) U12.N4(ESR2_VBATT) U12.P2(ESR1_VBATT)
N137369: ESD11.1 J17.3(DAT+) R31.1
N350266: R30.2 U12.B4(ATP_RST_B) U12.E23(POR_B)
N352539: R24.2 U12.L22(BATT_ISET)
N364156: L12.2 U12.P4(ESR3_LX)
N380754: C35.1 U12.K1(BUCK_VOUT)
N385362: J18.1(ANT-IN) R18.2
N385382: RLC10.2 RLC11.2
N385442: C37.2 R19.2 RLC10.1
N441562: ESD10.1 J17.2(DAT-) R32.1
N463771: C45.1 U12.N2(VDD_PLAT_3P3)
N498391: C20.1 R35.1 U12.G22(COMP_AREF) U12.H23(ADC_3P3_VCC)
N521217: C17.1 R59.1 U12.K4(VDD_USB)
N544606: C12.1 C16.1 D18.K R77.1 U10.10(AVIN) U10.11(PVIN1) U10.12(PVIN2)
N545273: L10.1 U10.1(SW1) U10.2(SW2) U10.3(SW3)
N616057: C48.1 U12.L1(LDO1P8_VOUT)
N656910: C51.1 R27.2 U15.19(VREF_B) U15.20(EN)
N656990: C53.1 R29.2 U11.19(VREF_B) U11.20(EN)
N657094: C52.1 R28.2 U14.19(VREF_B) U14.20(EN)
N692018: R73.2 R74.1 SH10.1(P1)
N692192: R74.2 U13.C2(ISET)
N704436: C15.1 U10.9(SS/TR)
N704444: R70.2 R71.1 U10.8(DEF)
N724575: C41.1 R23.1 SW12.1 SW12.2
N724587: C19.1 R13.1 SW10.3 SW10.4
N726409: D10.A R10.2
N726427: D14.A R15.2
N726455: D15.A R16.2
N761735: D13.A R14.2
N761736: R14.1 U16.4(Y)
N765836: C54.1 R82.1 R83.2 U202.1(VDD)

Not connected (* = marked no-connect by the designer): J15 7(RTCK/KEY); U10 4(PG); U12 A21(6AXIS_SDA) A22(6AXIS_SCL) A23(6AXIS_INT2) B21(SPI1_M_CS2) B23(BLE_SDA) B24(BT_GPIO) C22(SPI1_M_CS3) D2(I2C1_SDA) E1(I2C1_SCL) E2(I2C1_SS_SDA) F1(I2C1_SS_SCL) F21(ATP_INT3) F23(BLE_SCL) G4(SPI0_SS_CS3) G23(BLE_DEC2) H3(SPI0_SS_CS1) H4(SPI0_SS_CS0) J1(AVD_OPM_2P6) J3(SPI0_SS_MISO) J4(SPI0_SS_SCK) K3(SPI0_SS_CS2) L3(ATP_INT2) M3(SPI0_SS_MOSI) M4(ESR2_LX) M22(CHG_STATUS) M24(I2C0_SCL) N1(ESR1_LX) N3(ATP_INT1) N22(BATT_TEMP) P21(SW_FG_VBATT) P23(I2C0_SDA); U13 C1(OC_FLAG); U15 3(A1) 4(A2) 17(B2) 18(B1); U16 1(NC); U202 5(C_DLY)

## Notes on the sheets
sheet 1
- Intel® Curie™ Design Document
  This Intel® Curie™ design document is licensed by Intel under the
   terms of the Creative Commons Attribution Share-Alike License
   (ver. 3), subject to the following terms and conditions. The Intel®
   Curie™ design document IS PROVIDED "AS IS" AND "WITH
   ALL FAULTS." Intel DISCLAIMS ALL OTHER WARRANTIES,
  EXPRESS OR IMPLIED REGARDING THE CURIE DESIGN OR
  THIS CURIE DESIGN DOCUMENT INCLUDING, BUT NOT
  LIMITED TO, ANY IMPLIED WARRANTIES OF
  MERCHANTABILITY OR FITNESS FOR A PARTICULAR
  PURPOSE. Intel® may make changes to the specifications,
  schematics and product descriptions at any time, without notice.
  The Customer must not rely on the absence or characteristics of
  any features or instructions marked "reserved" or "undefined."
  Intel® reserves these for future definition and shall have no
  responsibility whatsoever for conflicts or incompatibilities arising
  from future changes to them.
   ENJOY!
- EE:M.KASHI,S.VANGENT
sheet 2
- I/O
- Antenna
- Power and reset
- Internal ANT
- JTAG
- USB DIFF SIGNALS
- Test Points
- Test JTAG
- 3V Buck not used
- 1.8V Buck not used
- EE:M.KASHI,S.VANGENT
sheet 3
- Power Input SEL
- USB Power Input
- CURRENT LIMITS RESISTOR VALUES
  2100=500mA; 698 = 1.5A; 1100 = 1A
  Short for 1.5A
- Trip set to 5.75V
- Barrel  Power Input
- 20V tolerant
- 7-17VDC IN
- GENW BOARD SPECIFIC
- Com
- Fault
- MARK "L"
- RESET SKETCH
- Power
- Master reset-
- EE:M.KASHI,S.VANGENT
sheet 4
- EE:M.KASHI,S.VANGENT
- Intel® Curie™ Design Document
  This Intel® Curie™ design document is licensed by Intel under the
   terms of the Creative Commons Attribution Share-Alike License
   (ver. 3), subject to the following terms and conditions. The Intel®
   Curie™ design document IS PROVIDED "AS IS" AND "WITH
   ALL FAULTS." Intel DISCLAIMS ALL OTHER WARRANTIES,
  EXPRESS OR IMPLIED REGARDING THE CURIE DESIGN OR
  THIS CURIE DESIGN DOCUMENT INCLUDING, BUT NOT
  LIMITED TO, ANY IMPLIED WARRANTIES OF
  MERCHANTABILITY OR FITNESS FOR A PARTICULAR
  PURPOSE. Intel® may make changes to the specifications,
  schematics and product descriptions at any time, without notice.
  The Customer must not rely on the absence or characteristics of
  any features or instructions marked "reserved" or "undefined."
  Intel® reserves these for future definition and shall have no
  responsibility whatsoever for conflicts or incompatibilities arising
  from future changes to them.
   ENJOY!
- EE:M.KASHI,S.VANGENT
